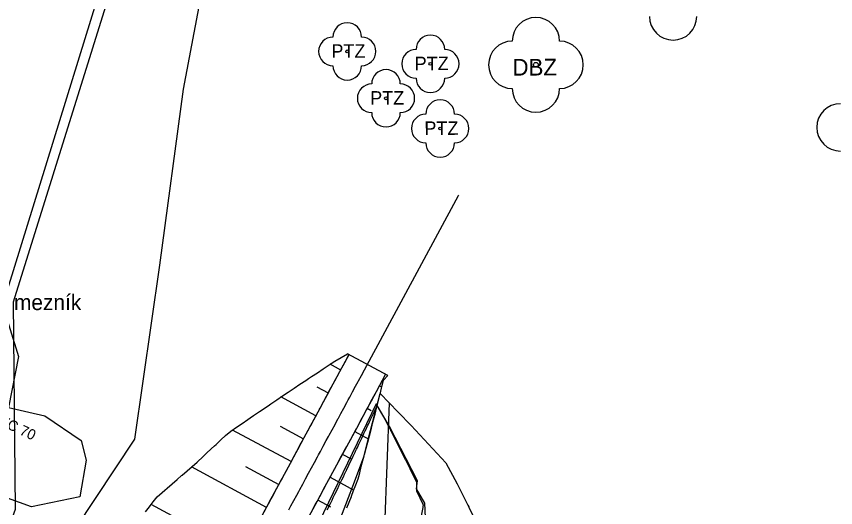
# Model space of a CAD drawing. Extents: x -564037 to -563722, y -1163561 to -1163412.
# Drawn here: x -563977.45 to -563938.1, y -1163469.97 to -1163446.37 of the extents above; entities that cross this region are included whole.
import ezdxf

# ---------------------------------------------------------------- set-up
doc = ezdxf.new("R2010")
doc.units = 0
for name, color, linetype in [('Default', 7, 'Continuous'), ('Definiční bod kú', 7, 'Continuous'), ('Hranice parcel', 7, 'Continuous'), ('Line', 7, 'Continuous'), ('Vrstva 1', 7, 'Continuous'), ('Vrstva 14', 7, 'Continuous'), ('Vrstva 2', 7, 'Continuous'), ('Vrstva 41', 7, 'Continuous')]:
    doc.layers.add(name, color=color, linetype=linetype)

msp = doc.modelspace()

# ---------------------------------------------------------------- linework, layer by layer
for points in [[(-563982.839, -1163488.47), (-563983.409, -1163491.846), (-563990.891, -1163500.051), (-563993.495, -1163501.54), (-564001.695, -1163505.76), (-564021.072, -1163514.028), (-564021.939, -1163519.359), (-564028.021, -1163535.92), (-563982.332, -1163543.556), (-563870.708, -1163549.442), (-563829.278, -1163493.346), (-563857.264, -1163473.56), (-563873.956, -1163464.96), (-563885.354, -1163462.845), (-563964.187, -1163417.135), (-563977.612, -1163460.096), (-563977.509, -1163470.055), (-563981.031, -1163479.642), (-563982.839, -1163488.47)], [(-563964.365, -1163470.07), (-563964.265, -1163469.884), (-563964.123, -1163469.623), (-563963.982, -1163469.362), (-563963.89, -1163469.19), (-563963.841, -1163469.1), (-563963.7, -1163468.839), (-563963.559, -1163468.578), (-563963.418, -1163468.317), (-563963.415, -1163468.31), (-563963.277, -1163468.056), (-563963.136, -1163467.795), (-563962.995, -1163467.534), (-563962.94, -1163467.43), (-563962.854, -1163467.272), (-563962.713, -1163467.011), (-563962.572, -1163466.75), (-563962.464, -1163466.55), (-563962.431, -1163466.489), (-563962.29, -1163466.228), (-563962.149, -1163465.967), (-563962.008, -1163465.706), (-563961.989, -1163465.67), (-563961.867, -1163465.444), (-563961.726, -1163465.183), (-563961.585, -1163464.922), (-563961.514, -1163464.79), (-563961.444, -1163464.661), (-563961.303, -1163464.4), (-563961.162, -1163464.139), (-563961.039, -1163463.911), (-563961.021, -1163463.878), (-563960.88, -1163463.616), (-563960.739, -1163463.355), (-563956.21, -1163454.967), (-563956.209, -1163454.966)], [(-563971.248, -1163470.161), (-563971.063, -1163469.923), (-563971.03, -1163469.88), (-563970.878, -1163469.686), (-563970.688, -1163469.451), (-563970.451, -1163469.242), (-563970.321, -1163469.127), (-563970.213, -1163469.033), (-563969.975, -1163468.824), (-563969.736, -1163468.616), (-563969.517, -1163468.425), (-563969.497, -1163468.407), (-563969.258, -1163468.2), (-563969.018, -1163467.992), (-563968.777, -1163467.784), (-563968.71, -1163467.724), (-563968.548, -1163467.571), (-563968.319, -1163467.357), (-563968.091, -1163467.143), (-563967.94, -1163467.003), (-563967.862, -1163466.93), (-563967.632, -1163466.716), (-563967.402, -1163466.503), (-563967.157, -1163466.298), (-563967.15, -1163466.293), (-563966.883, -1163466.109), (-563966.608, -1163465.92), (-563966.333, -1163465.731), (-563966.224, -1163465.657), (-563966.057, -1163465.543), (-563965.782, -1163465.355), (-563965.505, -1163465.167), (-563965.293, -1163465.023), (-563965.228, -1163464.979), (-563964.951, -1163464.791), (-563964.673, -1163464.604), (-563964.395, -1163464.417), (-563964.358, -1163464.392), (-563964.117, -1163464.23), (-563963.838, -1163464.043), (-563963.558, -1163463.857), (-563963.417, -1163463.763), (-563963.279, -1163463.671), (-563962.998, -1163463.485), (-563962.718, -1163463.299), (-563962.472, -1163463.137), (-563962.437, -1163463.113), (-563962.154, -1163462.929), (-563961.854, -1163462.754), (-563961.553, -1163462.579), (-563961.551, -1163462.577)], [(-563971.248, -1163470.161), (-563971.063, -1163469.923), (-563971.03, -1163469.88), (-563970.878, -1163469.686), (-563970.688, -1163469.451), (-563970.451, -1163469.242), (-563970.321, -1163469.127), (-563970.213, -1163469.033), (-563969.975, -1163468.824), (-563969.736, -1163468.616), (-563969.517, -1163468.425), (-563969.497, -1163468.407), (-563969.258, -1163468.2), (-563969.018, -1163467.992), (-563968.777, -1163467.784), (-563968.71, -1163467.724), (-563968.548, -1163467.571), (-563968.319, -1163467.357), (-563968.091, -1163467.143), (-563967.94, -1163467.003), (-563967.862, -1163466.93), (-563967.632, -1163466.716), (-563967.402, -1163466.503), (-563967.157, -1163466.298), (-563967.15, -1163466.293), (-563966.883, -1163466.109), (-563966.608, -1163465.92), (-563966.333, -1163465.731), (-563966.224, -1163465.657), (-563966.057, -1163465.543), (-563965.782, -1163465.355), (-563965.505, -1163465.167), (-563965.293, -1163465.023), (-563965.228, -1163464.979), (-563964.951, -1163464.791), (-563964.673, -1163464.604), (-563964.395, -1163464.417), (-563964.358, -1163464.392), (-563964.117, -1163464.23), (-563963.838, -1163464.043), (-563963.558, -1163463.857), (-563963.417, -1163463.763), (-563963.279, -1163463.671), (-563962.998, -1163463.485), (-563962.718, -1163463.299), (-563962.472, -1163463.137), (-563962.437, -1163463.113), (-563962.154, -1163462.929), (-563961.854, -1163462.754), (-563961.553, -1163462.579), (-563961.551, -1163462.577)], [(-563965.72, -1163470.475), (-563965.245, -1163469.595), (-563964.77, -1163468.715), (-563964.295, -1163467.835), (-563963.82, -1163466.955), (-563963.344, -1163466.075), (-563962.869, -1163465.195), (-563962.394, -1163464.315), (-563962.159, -1163463.88), (-563961.919, -1163463.435), (-563961.477, -1163462.617)], [(-563965.567, -1163470.192), (-563965.426, -1163469.931), (-563965.285, -1163469.67), (-563965.245, -1163469.595), (-563965.144, -1163469.409), (-563965.003, -1163469.148), (-563964.862, -1163468.887), (-563964.77, -1163468.715), (-563964.721, -1163468.625), (-563964.58, -1163468.364), (-563964.439, -1163468.103), (-563964.298, -1163467.842), (-563964.295, -1163467.835), (-563964.157, -1163467.581), (-563964.016, -1163467.32), (-563963.875, -1163467.058), (-563963.82, -1163466.955), (-563963.734, -1163466.797), (-563963.593, -1163466.536), (-563963.452, -1163466.275), (-563963.344, -1163466.075), (-563963.311, -1163466.014), (-563963.17, -1163465.753), (-563963.029, -1163465.492), (-563962.888, -1163465.23), (-563962.869, -1163465.195), (-563962.747, -1163464.969), (-563962.606, -1163464.708), (-563962.465, -1163464.447), (-563962.394, -1163464.315), (-563962.324, -1163464.186), (-563962.183, -1163463.925), (-563962.042, -1163463.664), (-563961.919, -1163463.435), (-563961.901, -1163463.402), (-563961.76, -1163463.141), (-563961.619, -1163462.88), (-563961.478, -1163462.619), (-563961.477, -1163462.617)], [(-563959.822, -1163463.85), (-563959.62, -1163463.622), (-563959.618, -1163463.621), (-563961.551, -1163462.577)], [(-563963.485, -1163470.545), (-563963.01, -1163469.665), (-563962.535, -1163468.785), (-563962.06, -1163467.905), (-563961.585, -1163467.025), (-563961.109, -1163466.146), (-563960.634, -1163465.266), (-563960.399, -1163464.83), (-563960.159, -1163464.386), (-563959.717, -1163463.568)], [(-563963.244, -1163470.098), (-563963.103, -1163469.837), (-563963.01, -1163469.665), (-563962.962, -1163469.576), (-563962.821, -1163469.314), (-563962.68, -1163469.053), (-563962.539, -1163468.792), (-563962.535, -1163468.785), (-563962.398, -1163468.531), (-563962.257, -1163468.27), (-563962.115, -1163468.009), (-563962.06, -1163467.905), (-563961.974, -1163467.748), (-563961.833, -1163467.486), (-563961.692, -1163467.225), (-563961.585, -1163467.025), (-563961.551, -1163466.964), (-563961.41, -1163466.703), (-563961.269, -1163466.442), (-563961.128, -1163466.181), (-563961.109, -1163466.146), (-563960.987, -1163465.92), (-563960.846, -1163465.658), (-563960.705, -1163465.397), (-563960.634, -1163465.266), (-563960.564, -1163465.136), (-563960.423, -1163464.875), (-563960.282, -1163464.614), (-563960.159, -1163464.386), (-563960.141, -1163464.353), (-563960, -1163464.092), (-563959.859, -1163463.83), (-563959.718, -1163463.569), (-563959.717, -1163463.568)], [(-563961.582, -1163469.983), (-563961.469, -1163469.707), (-563961.361, -1163469.428), (-563961.359, -1163469.42), (-563961.254, -1163469.148), (-563961.147, -1163468.869), (-563961.044, -1163468.587), (-563961.013, -1163468.471), (-563960.965, -1163468.293), (-563960.886, -1163467.998), (-563960.807, -1163467.704), (-563960.746, -1163467.478), (-563960.728, -1163467.409), (-563960.649, -1163467.114), (-563960.571, -1163466.819), (-563960.493, -1163466.524), (-563960.483, -1163466.484), (-563960.415, -1163466.228), (-563960.341, -1163465.932), (-563960.266, -1163465.635), (-563960.228, -1163465.485), (-563960.192, -1163465.337), (-563960.117, -1163465.04), (-563960.043, -1163464.743), (-563959.979, -1163464.483), (-563959.969, -1163464.445), (-563959.896, -1163464.148), (-563959.822, -1163463.85)], [(-563961.582, -1163469.983), (-563961.469, -1163469.707), (-563961.361, -1163469.428), (-563961.359, -1163469.42), (-563961.254, -1163469.148), (-563961.147, -1163468.869), (-563961.044, -1163468.587), (-563961.013, -1163468.471), (-563960.965, -1163468.293), (-563960.886, -1163467.998), (-563960.807, -1163467.704), (-563960.746, -1163467.478), (-563960.728, -1163467.409), (-563960.649, -1163467.114), (-563960.571, -1163466.819), (-563960.493, -1163466.524), (-563960.483, -1163466.484), (-563960.415, -1163466.228), (-563960.341, -1163465.932), (-563960.266, -1163465.635), (-563960.228, -1163465.485), (-563960.192, -1163465.337), (-563960.117, -1163465.04), (-563960.043, -1163464.743), (-563959.979, -1163464.483), (-563959.969, -1163464.445), (-563959.896, -1163464.148), (-563959.822, -1163463.85)], [(-563959.822, -1163463.85), (-563959.62, -1163463.622), (-563959.618, -1163463.621)], [(-563961.948, -1163470.647), (-563961.634, -1163469.818), (-563961.634, -1163469.816), (-563961.172, -1163468.595), (-563960.769, -1163467.532), (-563960.441, -1163466.264), (-563959.982, -1163464.487), (-563959.119, -1163465.38), (-563958.498, -1163466.022), (-563956.824, -1163467.815), (-563956.278, -1163468.828), (-563955.769, -1163469.847), (-563955.726, -1163469.933), (-563955.721, -1163469.943), (-563955.508, -1163470.369)]]:
    msp.add_lwpolyline(points)
msp.add_lwpolyline([(-563976.663, -1163501.462), (-563964.742, -1163493.091), (-563961.829, -1163491.15), (-563957.41, -1163486.988), (-563956.735, -1163486.627), (-563953.281, -1163481.221), (-563953.993, -1163478.343), (-563957.796, -1163470.824), (-563957.81, -1163470.439), (-563957.835, -1163469.754), (-563958.239, -1163469.063), (-563958.187, -1163468.683), (-563959.529, -1163466.077), (-563960.166, -1163464.984), (-563964.31, -1163473.527), (-563966.903, -1163478.544), (-563968.406, -1163481.669), (-563970.316, -1163485.955), (-563973.278, -1163492.988), (-563976.735, -1163500.155), (-563977.161, -1163500.889), (-563977.363, -1163501.307)], close=True)
at = {"layer": 'Default'}
msp.add_lwpolyline([(-563962.52, -1163470.075), (-563962.464, -1163469.96), (-563962.448, -1163469.927), (-563962.427, -1163469.884), (-563962.368, -1163469.761), (-563962.291, -1163469.604), (-563962.232, -1163469.481), (-563962.155, -1163469.324), (-563962.099, -1163469.207), (-563962.027, -1163469.059), (-563962.024, -1163469.052), (-563962.02, -1163469.043), (-563961.96, -1163468.919), (-563961.884, -1163468.763), (-563961.824, -1163468.638), (-563961.749, -1163468.483), (-563961.688, -1163468.355), (-563961.614, -1163468.202), (-563961.604, -1163468.182), (-563961.593, -1163468.158), (-563961.539, -1163468.047), (-563961.479, -1163467.921), (-563961.414, -1163467.784), (-563961.345, -1163467.64), (-563961.276, -1163467.497), (-563961.21, -1163467.359), (-563961.185, -1163467.306), (-563961.16, -1163467.255), (-563961.116, -1163467.161), (-563961.076, -1163467.078), (-563961.001, -1163466.92), (-563960.942, -1163466.797), (-563960.863, -1163466.629), (-563960.809, -1163466.516), (-563960.76, -1163466.414), (-563960.73, -1163466.35), (-563960.696, -1163466.277), (-563960.675, -1163466.234), (-563960.583, -1163466.04), (-563960.542, -1163465.953), (-563960.441, -1163465.739), (-563960.409, -1163465.671), (-563960.321, -1163465.483), (-563960.303, -1163465.445), (-563960.28, -1163465.398), (-563960.276, -1163465.389), (-563960.146, -1163465.112), (-563960.144, -1163465.107), (-563960.131, -1163465.079), (-563960.127, -1163465.084), (-563960.108, -1163465.118), (-563960.096, -1163465.137), (-563960.094, -1163465.14), (-563959.928, -1163465.421), (-563959.903, -1163465.465), (-563959.819, -1163465.606), (-563959.746, -1163465.731), (-563959.59, -1163466.042), (-563959.542, -1163466.129), (-563959.531, -1163466.151), (-563959.504, -1163466.204), (-563959.476, -1163466.26), (-563959.44, -1163466.331), (-563959.388, -1163466.435), (-563959.345, -1163466.522), (-563959.321, -1163466.569), (-563958.779, -1163467.65), (-563958.779, -1163467.651), (-563958.766, -1163467.675), (-563958.749, -1163467.71), (-563958.674, -1163467.859), (-563958.608, -1163467.992), (-563958.557, -1163468.092), (-563958.548, -1163468.111), (-563958.542, -1163468.123), (-563958.535, -1163468.137), (-563958.235, -1163468.735), (-563958.236, -1163468.829), (-563958.238, -1163468.946), (-563958.239, -1163469.057), (-563958.239, -1163469.063), (-563958.24, -1163469.164), (-563957.924, -1163469.795), (-563957.923, -1163469.823), (-563957.917, -1163469.836), (-563957.917, -1163469.837), (-563957.916, -1163469.837), (-563957.931, -1163469.905), (-563957.93, -1163469.959), (-563957.93, -1163469.965), (-563958.016, -1163470.367)], dxfattribs=at)
at = {"layer": 'Definiční bod kú'}
msp.add_lwpolyline([(-564036.505, -1163529.976), (-564035.88, -1163528.59), (-564032.62, -1163523.46), (-564027.5, -1163518.53), (-564023.88, -1163515.79), (-564019.18, -1163512.89), (-564014.48, -1163510.5), (-564004.65, -1163507.04), (-563996.46, -1163502.51), (-563993.72, -1163500.97), (-563990.58, -1163498.69), (-563987.18, -1163495.32), (-563983.19, -1163487.81), (-563979.82, -1163480.39), (-563975.55, -1163472.37), (-563971.76, -1163466.68), (-563970.57, -1163458.32), (-563969.42, -1163449.87), (-563967.93, -1163441.99), (-563966.12, -1163434.66), (-563963.95, -1163427.04), (-563963.19, -1163422.98), (-563961.48, -1163418.93), (-563957.126, -1163412.494)], dxfattribs=at)
at = {"layer": 'Hranice parcel'}
msp.add_line((-563964.47, -1163416.08), (-563978.16, -1163460.35), dxfattribs=at)
at = {"layer": 'Line'}
for p, q in [((-563961.877, -1163463.358), (-563962.389, -1163463.082)), ((-563963.021, -1163464.162), (-563962.471, -1163464.458)), ((-563960.011, -1163464.111), (-563959.901, -1163464.17)), ((-563963.065, -1163465.558), (-563964.744, -1163464.652)), ((-563959.553, -1163464.931), (-563960.089, -1163479.118)), ((-563960.409, -1163465.316), (-563960.605, -1163465.211)), ((-563964.253, -1163467.758), (-563967.069, -1163466.238)), ((-563964.785, -1163466.05), (-563963.659, -1163466.658)), ((-563961.199, -1163466.311), (-563960.532, -1163466.671)), ((-563961.328, -1163467.661), (-563961.792, -1163467.41)), ((-563965.441, -1163469.958), (-563969.042, -1163468.013)), ((-563966.456, -1163467.989), (-563964.847, -1163468.858)), ((-563962.386, -1163468.51), (-563961.246, -1163469.126)), ((-563962.348, -1163469.952), (-563962.98, -1163469.61)), ((-563966.629, -1163472.158), (-563970.976, -1163469.81))]:
    msp.add_line(p, q, dxfattribs=at)
at = {"layer": 'Vrstva 14'}
msp.add_lwpolyline([(-563978.09, -1163460.32), (-563977.36, -1163462.71), (-563977.84, -1163465.15), (-563976.09, -1163465.55), (-563974.34, -1163466.75), (-563974.1, -1163467.69), (-563974.4, -1163469.44), (-563976.73, -1163469.93), (-563977.88, -1163469.51), (-563978.75, -1163470.09), (-563979.22, -1163471.2), (-563981.47, -1163479.57), (-563983.82, -1163487.72), (-563987.7, -1163494.99), (-563990.79, -1163498.34), (-563994.06, -1163500.55), (-563996.65, -1163502.12), (-564005.13, -1163506.34), (-564014.58, -1163510.01)], dxfattribs=at)
at = {"layer": 'Vrstva 2'}
for centre, radius in [((-563961.563, -1163448.054), 0.0688), ((-563957.566, -1163448.65), 0.0688), ((-563952.501, -1163448.699), 0.114), ((-563952.501, -1163448.699), 0.114), ((-563959.7, -1163450.304), 0.0688), ((-563957.098, -1163451.756), 0.0688)]:
    msp.add_circle(centre, radius, dxfattribs=at)
for centre, radius, start, end in [((-563952.501, -1163447.562), 1.137, 0, 180), ((-563952.501, -1163447.562), 1.137, 0, 180), ((-563945.909, -1163446.372), 1.137, 180, 0), ((-563961.563, -1163447.366), 0.688, 0, 180), ((-563962.251, -1163448.054), 0.688, 90, 270), ((-563960.876, -1163448.054), 0.688, 270, 90), ((-563957.566, -1163447.962), 0.688, 0, 180), ((-563953.638, -1163448.699), 1.137, 90, 270), ((-563953.638, -1163448.699), 1.137, 90, 270), ((-563951.363, -1163448.699), 1.137, 270, 90), ((-563951.363, -1163448.699), 1.137, 270, 90), ((-563958.254, -1163448.65), 0.688, 90, 270), ((-563956.878, -1163448.65), 0.688, 270, 90), ((-563961.563, -1163448.742), 0.688, 180, 0), ((-563959.7, -1163449.616), 0.688, 0, 180), ((-563960.388, -1163450.304), 0.688, 90, 270), ((-563959.012, -1163450.304), 0.688, 270, 90), ((-563957.566, -1163449.338), 0.688, 180, 0), ((-563952.501, -1163449.836), 1.137, 180, 0), ((-563952.501, -1163449.836), 1.137, 180, 0), ((-563957.098, -1163451.068), 0.688, 0, 180), ((-563937.87, -1163451.704), 1.137, 90, 270), ((-563959.7, -1163450.992), 0.688, 180, 0), ((-563957.786, -1163451.756), 0.688, 90, 270), ((-563956.41, -1163451.756), 0.688, 270, 90), ((-563957.098, -1163452.444), 0.688, 180, 0)]:
    msp.add_arc(centre, radius, start, end, dxfattribs=at)

# ---------------------------------------------------------------- texts
at = {"layer": 'Vrstva 1'}
for s, height, p in [('PTZ', 0.648, (-563962.323, -1163448.362)), ('PTZ', 0.648, (-563958.325, -1163448.958)), ('DBZ', 0.8, (-563953.624, -1163449.215)), ('PTZ', 0.648, (-563960.46, -1163450.612)), ('PTZ', 0.648, (-563957.857, -1163452.065))]:
    msp.add_text(s, height=height, rotation=0.1546, dxfattribs=at).set_placement(p)
at = {"layer": 'Vrstva 41'}
msp.add_text('mezník', height=0.75, dxfattribs=at).set_placement((-563977.57, -1163460.48))
msp.add_text('potrubí PVC 70', height=0.5, rotation=334.9419, dxfattribs=at).set_placement((-563980.81, -1163464.81))

doc.saveas('drawing.dxf')
